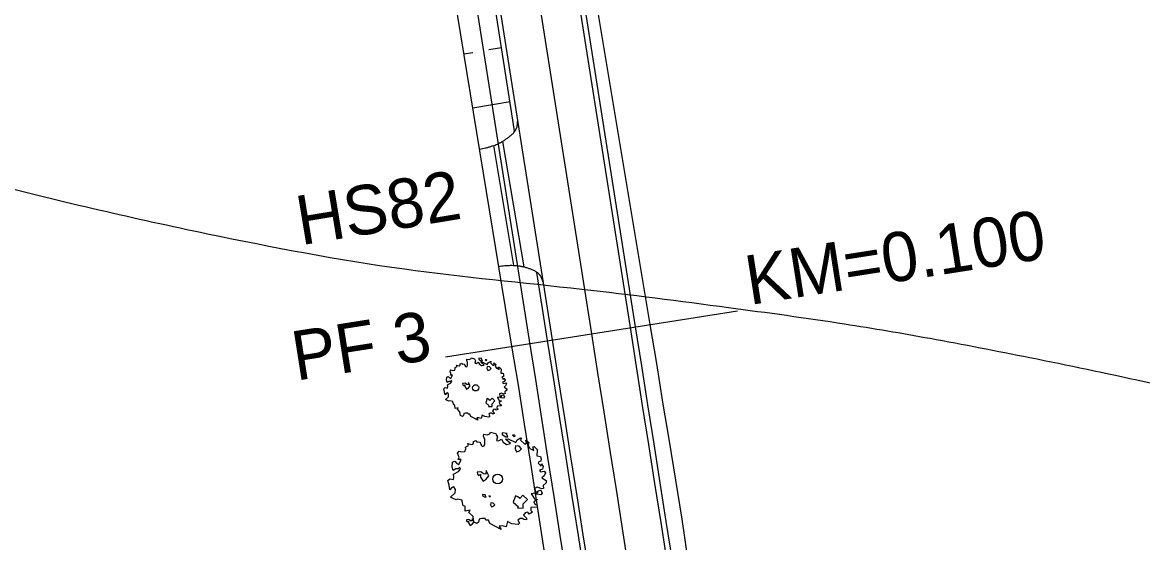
# Model space of a CAD drawing. Extents: x -477701 to -476785, y -1116511 to -1115314.
# Drawn here: x -477049.9 to -476993.1, y -1116046.9 to -1116020.5 of the extents above; entities that cross this region are included whole.
import ezdxf

# ---------------------------------------------------------------- set-up
doc = ezdxf.new("R2010")
doc.units = 0
for name, color, linetype in [('hrana_P', 7, 'Continuous'), ('hrana_R', 7, 'Continuous'), ('IP_RBK', 7, 'Continuous'), ('POLYGONY_SITUACE_PF', 7, 'Continuous'), ('POLYGONY_SITUACE_PF_POPISY', 7, 'Continuous'), ('popis', 7, 'Continuous'), ('svahování', 7, 'Continuous'), ('TP_HS', 7, 'Continuous'), ('Vrstevnice_hlavni', 7, 'Continuous'), ('Vrstevnice_vedlejsi', 7, 'Continuous')]:
    doc.layers.add(name, color=color, linetype=linetype)

msp = doc.modelspace()

# ---------------------------------------------------------------- linework, layer by layer
at = {"layer": 'hrana_P'}
for points in [[(-477018.038, -1116035.808), (-477021.004, -1116018.053)], [(-477025.047, -1116036.913), (-477027.968, -1116019.151)], [(-477017.702, -1116037.779), (-477018.038, -1116035.808)], [(-477024.724, -1116038.886), (-477025.047, -1116036.913)], [(-477017.388, -1116039.755), (-477017.702, -1116037.779)], [(-477024.411, -1116040.862), (-477024.724, -1116038.886)], [(-477017.053, -1116041.726), (-477017.388, -1116039.755)], [(-477024.099, -1116042.837), (-477024.411, -1116040.862)], [(-477016.736, -1116043.701), (-477017.053, -1116041.726)], [(-477023.795, -1116044.814), (-477024.099, -1116042.837)], [(-477016.423, -1116045.677), (-477016.736, -1116043.701)], [(-477023.49, -1116046.791), (-477023.795, -1116044.814)], [(-477016.123, -1116047.654), (-477016.423, -1116045.677)], [(-477023.184, -1116048.767), (-477023.49, -1116046.791)]]:
    msp.add_lwpolyline(points, dxfattribs=at)
at = {"layer": 'hrana_R'}
for points in [[(-477019.042, -1116035.966), (-477021.845, -1116018.185)], [(-477021.598, -1116018.147), (-477018.795, -1116035.927)], [(-477024.158, -1116036.628), (-477026.961, -1116018.847)], [(-477024.917, -1116025.985), (-477026.043, -1116018.847)], [(-477022.993, -1116036.589), (-477025.796, -1116018.808)], [(-477023.82, -1116018.497), (-477021.017, -1116036.277)], [(-477023.24, -1116036.628), (-477023.784, -1116033.172)], [(-477018.73, -1116037.941), (-477019.042, -1116035.966)], [(-477018.795, -1116035.927), (-477018.483, -1116037.903)], [(-477022.681, -1116038.564), (-477022.993, -1116036.589)], [(-477021.017, -1116036.277), (-477020.706, -1116038.253)], [(-477023.846, -1116038.603), (-477024.158, -1116036.628)], [(-477022.928, -1116038.603), (-477023.24, -1116036.628)], [(-477020.706, -1116038.253), (-477020.394, -1116040.229)], [(-477018.419, -1116039.917), (-477018.73, -1116037.941)], [(-477018.483, -1116037.903), (-477018.172, -1116039.878)], [(-477023.535, -1116040.579), (-477023.846, -1116038.603)], [(-477022.617, -1116040.579), (-477022.928, -1116038.603)], [(-477022.37, -1116040.54), (-477022.681, -1116038.564)], [(-477018.107, -1116041.893), (-477018.419, -1116039.917)], [(-477018.172, -1116039.878), (-477017.86, -1116041.854)], [(-477023.223, -1116042.554), (-477023.535, -1116040.579)], [(-477022.305, -1116042.554), (-477022.617, -1116040.579)], [(-477022.058, -1116042.516), (-477022.37, -1116040.54)], [(-477020.394, -1116040.229), (-477020.083, -1116042.204)], [(-477020.083, -1116042.204), (-477019.771, -1116044.18)], [(-477017.796, -1116043.868), (-477018.107, -1116041.893)], [(-477017.86, -1116041.854), (-477017.549, -1116043.829)], [(-477022.912, -1116044.53), (-477023.223, -1116042.554)], [(-477021.994, -1116044.53), (-477022.305, -1116042.554)], [(-477021.747, -1116044.491), (-477022.058, -1116042.516)], [(-477017.484, -1116045.844), (-477017.796, -1116043.868)], [(-477017.549, -1116043.829), (-477017.237, -1116045.805)], [(-477022.6, -1116046.506), (-477022.912, -1116044.53)], [(-477021.682, -1116046.506), (-477021.994, -1116044.53)], [(-477021.436, -1116046.467), (-477021.747, -1116044.491)], [(-477019.771, -1116044.18), (-477019.46, -1116046.155)], [(-477019.46, -1116046.155), (-477019.148, -1116048.131)], [(-477017.173, -1116047.819), (-477017.484, -1116045.844)], [(-477017.237, -1116045.805), (-477016.926, -1116047.781)], [(-477022.289, -1116048.481), (-477022.6, -1116046.506)], [(-477021.371, -1116048.481), (-477021.682, -1116046.506)], [(-477021.124, -1116048.442), (-477021.436, -1116046.467)]]:
    msp.add_lwpolyline(points, dxfattribs=at)
at = {"layer": 'IP_RBK'}
for points in [[(-477025.969, -1116037.759), (-477025.874, -1116037.832), (-477025.896, -1116037.915), (-477025.837, -1116038.028), (-477025.703, -1116038.089), (-477025.745, -1116037.98), (-477025.695, -1116037.964), (-477025.58, -1116038.088), (-477025.603, -1116038.081), (-477025.612, -1116038.271), (-477025.495, -1116038.284), (-477025.47, -1116038.367), (-477025.484, -1116038.443), (-477025.551, -1116038.459), (-477025.57, -1116038.504), (-477025.473, -1116038.602), (-477025.459, -1116038.522), (-477025.4, -1116038.614), (-477025.423, -1116038.7), (-477025.522, -1116038.732), (-477025.491, -1116038.792), (-477025.368, -1116038.766), (-477025.333, -1116038.825), (-477025.37, -1116038.913), (-477025.446, -1116038.986), (-477025.309, -1116039.068), (-477025.312, -1116039.146), (-477025.403, -1116039.23), (-477025.394, -1116039.329), (-477025.463, -1116039.344), (-477025.585, -1116039.286), (-477025.678, -1116039.317), (-477025.662, -1116039.419), (-477025.575, -1116039.473), (-477025.582, -1116039.419), (-477025.538, -1116039.395), (-477025.481, -1116039.383), (-477025.434, -1116039.481), (-477025.476, -1116039.538), (-477025.62, -1116039.519), (-477025.67, -1116039.487), (-477025.793, -1116039.504), (-477025.78, -1116039.509), (-477025.69, -1116039.669), (-477025.585, -1116039.682), (-477025.706, -1116039.761), (-477025.681, -1116039.838), (-477025.596, -1116039.874), (-477025.598, -1116039.937), (-477025.807, -1116039.948), (-477025.811, -1116040.05), (-477025.753, -1116040.1), (-477025.858, -1116040.16), (-477025.902, -1116040.095), (-477025.989, -1116040.115), (-477026.042, -1116040.195), (-477025.95, -1116040.289), (-477025.95, -1116040.345), (-477026.036, -1116040.332), (-477026.081, -1116040.303), (-477026.159, -1116040.306), (-477026.228, -1116040.359), (-477026.178, -1116040.461), (-477026.22, -1116040.5), (-477026.419, -1116040.479), (-477026.566, -1116040.401), (-477026.604, -1116040.574), (-477026.738, -1116040.539), (-477026.832, -1116040.549), (-477026.772, -1116040.657), (-477027.142, -1116040.466), (-477027.187, -1116040.362), (-477027.27, -1116040.358), (-477027.287, -1116040.31), (-477027.403, -1116040.307), (-477027.491, -1116040.325), (-477027.51, -1116040.425), (-477027.566, -1116040.47), (-477027.665, -1116040.419), (-477027.686, -1116040.237), (-477027.819, -1116040.107), (-477027.781, -1116040.036), (-477027.938, -1116040.064), (-477027.948, -1116039.907), (-477028.005, -1116039.89), (-477028.046, -1116039.746), (-477028.045, -1116039.712), (-477028.193, -1116039.672), (-477028.236, -1116039.696), (-477028.337, -1116039.659), (-477028.418, -1116039.607), (-477028.267, -1116039.473), (-477028.263, -1116039.366), (-477028.306, -1116039.274), (-477028.376, -1116039.297), (-477028.445, -1116039.378), (-477028.464, -1116039.225), (-477028.502, -1116039.067), (-477028.44, -1116039.011), (-477028.319, -1116039.038), (-477028.307, -1116038.958), (-477028.327, -1116038.861), (-477028.162, -1116038.776), (-477028.099, -1116038.703), (-477028.111, -1116038.642), (-477028.173, -1116038.692), (-477028.247, -1116038.692), (-477028.333, -1116038.746), (-477028.368, -1116038.634), (-477028.358, -1116038.472), (-477028.281, -1116038.441), (-477028.215, -1116038.518), (-477028.145, -1116038.544), (-477028.08, -1116038.409), (-477028.073, -1116038.386), (-477028.173, -1116038.384), (-477028.135, -1116038.309), (-477028.164, -1116038.262), (-477028.191, -1116038.179), (-477028.134, -1116038.113), (-477028.068, -1116038.141), (-477027.953, -1116038.13), (-477027.924, -1116038.041), (-477027.936, -1116037.986), (-477027.835, -1116037.93), (-477027.861, -1116037.87), (-477027.729, -1116037.898), (-477027.671, -1116037.865), (-477027.674, -1116037.798), (-477027.587, -1116037.769), (-477027.578, -1116037.814), (-477027.526, -1116037.81), (-477027.47, -1116037.826), (-477027.448, -1116037.851), (-477027.438, -1116037.894), (-477027.411, -1116037.932), (-477027.376, -1116037.959), (-477027.323, -1116037.943), (-477027.3, -1116037.879), (-477027.299, -1116037.738), (-477027.346, -1116037.629), (-477027.341, -1116037.562), (-477027.224, -1116037.581), (-477027.14, -1116037.553), (-477027.12, -1116037.503), (-477026.945, -1116037.542), (-477026.931, -1116037.586), (-477026.891, -1116037.647), (-477026.927, -1116037.773), (-477026.864, -1116037.778), (-477026.764, -1116037.722), (-477026.701, -1116037.823), (-477026.595, -1116037.894), (-477026.465, -1116037.866), (-477026.628, -1116037.723), (-477026.541, -1116037.716), (-477026.299, -1116037.829), (-477026.246, -1116037.743), (-477026.138, -1116037.678), (-477026.109, -1116037.691), (-477026.14, -1116037.758), (-477026.007, -1116037.889), (-477025.945, -1116037.861)], [(-477026.737, -1116037.573), (-477026.624, -1116037.645), (-477026.55, -1116037.654), (-477026.597, -1116037.555), (-477026.577, -1116037.54), (-477026.736, -1116037.517)], [(-477026.401, -1116037.594), (-477026.352, -1116037.645), (-477026.321, -1116037.62), (-477026.337, -1116037.598)], [(-477026.3, -1116037.944), (-477026.318, -1116038.045), (-477026.268, -1116038.141), (-477026.179, -1116038.108), (-477026.109, -1116038.041), (-477026.182, -1116037.954)], [(-477027.439, -1116038.868), (-477027.439, -1116038.96), (-477027.356, -1116039.089), (-477027.259, -1116039.027), (-477027.177, -1116038.915), (-477027.256, -1116038.748), (-477027.276, -1116038.861), (-477027.341, -1116038.85), (-477027.403, -1116038.805), (-477027.43, -1116038.785), (-477027.55, -1116038.8), (-477027.543, -1116038.86), (-477027.51, -1116038.909), (-477027.464, -1116038.89)], [(-477026.305, -1116039.563), (-477026.378, -1116039.773), (-477026.211, -1116039.928), (-477026.242, -1116039.962), (-477026.056, -1116039.967), (-477026.053, -1116039.826), (-477025.919, -1116039.683), (-477026.061, -1116039.549), (-477026.163, -1116039.658), (-477026.23, -1116039.595)], [(-477024.346, -1116041.676), (-477024.197, -1116041.79), (-477024.231, -1116041.919), (-477024.14, -1116042.095), (-477023.931, -1116042.191), (-477023.997, -1116042.02), (-477023.918, -1116041.996), (-477023.739, -1116042.189), (-477023.774, -1116042.178), (-477023.788, -1116042.474), (-477023.606, -1116042.494), (-477023.567, -1116042.624), (-477023.59, -1116042.742), (-477023.694, -1116042.766), (-477023.723, -1116042.837), (-477023.572, -1116042.99), (-477023.551, -1116042.866), (-477023.458, -1116043.009), (-477023.495, -1116043.143), (-477023.648, -1116043.193), (-477023.601, -1116043.287), (-477023.408, -1116043.245), (-477023.353, -1116043.338), (-477023.412, -1116043.475), (-477023.529, -1116043.588), (-477023.317, -1116043.717), (-477023.321, -1116043.839), (-477023.464, -1116043.969), (-477023.449, -1116044.123), (-477023.557, -1116044.147), (-477023.747, -1116044.056), (-477023.892, -1116044.105), (-477023.867, -1116044.263), (-477023.731, -1116044.348), (-477023.741, -1116044.264), (-477023.674, -1116044.226), (-477023.584, -1116044.208), (-477023.511, -1116044.361), (-477023.576, -1116044.45), (-477023.801, -1116044.42), (-477023.879, -1116044.369), (-477024.07, -1116044.396), (-477024.05, -1116044.404), (-477023.91, -1116044.653), (-477023.746, -1116044.674), (-477023.935, -1116044.797), (-477023.897, -1116044.918), (-477023.764, -1116044.974), (-477023.767, -1116045.072), (-477024.092, -1116045.088), (-477024.099, -1116045.248), (-477024.009, -1116045.325), (-477024.172, -1116045.419), (-477024.24, -1116045.318), (-477024.377, -1116045.35), (-477024.459, -1116045.473), (-477024.316, -1116045.621), (-477024.315, -1116045.708), (-477024.45, -1116045.688), (-477024.52, -1116045.642), (-477024.641, -1116045.647), (-477024.748, -1116045.73), (-477024.672, -1116045.889), (-477024.737, -1116045.95), (-477025.047, -1116045.917), (-477025.277, -1116045.795), (-477025.336, -1116046.065), (-477025.544, -1116046.01), (-477025.691, -1116046.027), (-477025.598, -1116046.195), (-477026.175, -1116045.896), (-477026.244, -1116045.734), (-477026.373, -1116045.728), (-477026.401, -1116045.653), (-477026.582, -1116045.649), (-477026.719, -1116045.676), (-477026.748, -1116045.833), (-477026.835, -1116045.903), (-477026.99, -1116045.823), (-477027.023, -1116045.539), (-477027.231, -1116045.337), (-477027.171, -1116045.225), (-477027.415, -1116045.27), (-477027.431, -1116045.025), (-477027.52, -1116044.998), (-477027.583, -1116044.774), (-477027.582, -1116044.721), (-477027.813, -1116044.658), (-477027.88, -1116044.696), (-477028.038, -1116044.638), (-477028.164, -1116044.557), (-477027.928, -1116044.347), (-477027.921, -1116044.181), (-477027.99, -1116044.038), (-477028.098, -1116044.073), (-477028.205, -1116044.2), (-477028.236, -1116043.962), (-477028.295, -1116043.715), (-477028.198, -1116043.628), (-477028.009, -1116043.669), (-477027.991, -1116043.546), (-477028.023, -1116043.395), (-477027.765, -1116043.261), (-477027.667, -1116043.147), (-477027.685, -1116043.053), (-477027.782, -1116043.13), (-477027.896, -1116043.13), (-477028.032, -1116043.214), (-477028.086, -1116043.04), (-477028.071, -1116042.787), (-477027.951, -1116042.739), (-477027.848, -1116042.859), (-477027.739, -1116042.899), (-477027.637, -1116042.689), (-477027.626, -1116042.653), (-477027.781, -1116042.651), (-477027.723, -1116042.533), (-477027.768, -1116042.46), (-477027.811, -1116042.33), (-477027.721, -1116042.228), (-477027.617, -1116042.272), (-477027.439, -1116042.255), (-477027.394, -1116042.116), (-477027.413, -1116042.03), (-477027.254, -1116041.943), (-477027.295, -1116041.849), (-477027.09, -1116041.892), (-477026.998, -1116041.84), (-477027.003, -1116041.736), (-477026.868, -1116041.691), (-477026.854, -1116041.761), (-477026.772, -1116041.755), (-477026.685, -1116041.781), (-477026.651, -1116041.819), (-477026.636, -1116041.886), (-477026.593, -1116041.945), (-477026.539, -1116041.987), (-477026.456, -1116041.963), (-477026.42, -1116041.863), (-477026.419, -1116041.643), (-477026.493, -1116041.473), (-477026.484, -1116041.368), (-477026.302, -1116041.399), (-477026.171, -1116041.354), (-477026.14, -1116041.276), (-477025.868, -1116041.337), (-477025.846, -1116041.405), (-477025.784, -1116041.501), (-477025.839, -1116041.698), (-477025.74, -1116041.706), (-477025.584, -1116041.618), (-477025.487, -1116041.776), (-477025.321, -1116041.886), (-477025.118, -1116041.843), (-477025.373, -1116041.62), (-477025.237, -1116041.608), (-477024.86, -1116041.785), (-477024.778, -1116041.65), (-477024.609, -1116041.55), (-477024.564, -1116041.57), (-477024.612, -1116041.674), (-477024.404, -1116041.878), (-477024.308, -1116041.834)], [(-477025.543, -1116041.385), (-477025.366, -1116041.497), (-477025.251, -1116041.512), (-477025.325, -1116041.358), (-477025.293, -1116041.334), (-477025.541, -1116041.299)], [(-477025.018, -1116041.418), (-477024.943, -1116041.497), (-477024.894, -1116041.459), (-477024.919, -1116041.425)], [(-477024.862, -1116041.965), (-477024.889, -1116042.121), (-477024.811, -1116042.272), (-477024.673, -1116042.22), (-477024.564, -1116042.116), (-477024.677, -1116041.979)], [(-477026.637, -1116043.405), (-477026.637, -1116043.548), (-477026.509, -1116043.749), (-477026.357, -1116043.653), (-477026.23, -1116043.478), (-477026.352, -1116043.218), (-477026.382, -1116043.394), (-477026.485, -1116043.376), (-477026.581, -1116043.306), (-477026.623, -1116043.276), (-477026.81, -1116043.298), (-477026.799, -1116043.392), (-477026.748, -1116043.468), (-477026.676, -1116043.438)], [(-477026.55, -1116044.48), (-477026.437, -1116044.552), (-477026.363, -1116044.562), (-477026.41, -1116044.463), (-477026.39, -1116044.448), (-477026.549, -1116044.425)], [(-477026.214, -1116044.502), (-477026.165, -1116044.552), (-477026.134, -1116044.528), (-477026.15, -1116044.506)], [(-477024.869, -1116044.489), (-477024.983, -1116044.817), (-477024.722, -1116045.058), (-477024.771, -1116045.111), (-477024.481, -1116045.118), (-477024.476, -1116044.898), (-477024.267, -1116044.676), (-477024.489, -1116044.467), (-477024.648, -1116044.637), (-477024.752, -1116044.539)], [(-477026.113, -1116044.852), (-477026.13, -1116044.953), (-477026.081, -1116045.049), (-477025.992, -1116045.016), (-477025.922, -1116044.949), (-477025.995, -1116044.861)], [(-477027.252, -1116045.776), (-477027.252, -1116045.867), (-477027.169, -1116045.997), (-477027.072, -1116045.935), (-477026.99, -1116045.823), (-477027.069, -1116045.656), (-477027.088, -1116045.769), (-477027.154, -1116045.757), (-477027.216, -1116045.712), (-477027.243, -1116045.693), (-477027.363, -1116045.707), (-477027.356, -1116045.768), (-477027.323, -1116045.817), (-477027.277, -1116045.797)]]:
    msp.add_lwpolyline(points, close=True, dxfattribs=at)
for centre, radius in [((-477026.886, -1116039.022), 0.158), ((-477025.775, -1116043.645), 0.247)]:
    msp.add_circle(centre, radius, dxfattribs=at)
at = {"layer": 'POLYGONY_SITUACE_PF'}
msp.add_lwpolyline([(-477028.425, -1116037.445), (-477021.017, -1116036.277), (-477013.608, -1116035.109)], dxfattribs=at)
at = {"layer": 'svahování'}
for points in [[(-477025.581, -1116021.773), (-477026.217, -1116021.879)], [(-477025.581, -1116021.773), (-477026.217, -1116021.879)], [(-477025.581, -1116021.773), (-477026.217, -1116021.879)], [(-477027.484, -1116022.092), (-477027.04, -1116022.017)], [(-477027.484, -1116022.092), (-477027.04, -1116022.017)], [(-477027.484, -1116022.092), (-477027.04, -1116022.017)], [(-477025.148, -1116024.525), (-477027.032, -1116024.841)], [(-477025.148, -1116024.525), (-477027.032, -1116024.841)], [(-477025.148, -1116024.525), (-477027.032, -1116024.841)]]:
    msp.add_lwpolyline(points, dxfattribs=at)
at = {"layer": 'TP_HS'}
for p, q in [((-477025.993, -1116026.74), (-477024.968, -1116032.81)), ((-477025.523, -1116026.524), (-477024.448, -1116032.883))]:
    msp.add_line(p, q, dxfattribs=at)
for points in [[(-477026.69, -1116026.92), (-477026.538, -1116026.893), (-477026.388, -1116026.857), (-477026.239, -1116026.816), (-477026.09, -1116026.772), (-477025.968, -1116026.732), (-477025.849, -1116026.685), (-477025.732, -1116026.633), (-477025.674, -1116026.605), (-477025.616, -1116026.576), (-477025.473, -1116026.494), (-477025.337, -1116026.403), (-477025.206, -1116026.303), (-477025.142, -1116026.25), (-477025.078, -1116026.195), (-477025.01, -1116026.133), (-477024.948, -1116026.066), (-477024.893, -1116025.994), (-477024.868, -1116025.955), (-477024.845, -1116025.914), (-477024.792, -1116025.783), (-477024.768, -1116025.647), (-477024.756, -1116025.42)], [(-477025.714, -1116032.854), (-477025.643, -1116032.844), (-477025.489, -1116032.828), (-477025.334, -1116032.817), (-477025.257, -1116032.814), (-477025.179, -1116032.81), (-477025.051, -1116032.808), (-477024.923, -1116032.813), (-477024.796, -1116032.823), (-477024.732, -1116032.831), (-477024.668, -1116032.839), (-477024.505, -1116032.869), (-477024.347, -1116032.911), (-477024.19, -1116032.962), (-477024.112, -1116032.991), (-477024.034, -1116033.021), (-477023.949, -1116033.058), (-477023.869, -1116033.1), (-477023.793, -1116033.15), (-477023.757, -1116033.179), (-477023.721, -1116033.21), (-477023.672, -1116033.261), (-477023.649, -1116033.288), (-477023.628, -1116033.316), (-477023.561, -1116033.437), (-477023.475, -1116033.648)]]:
    msp.add_spline(points, degree=3, dxfattribs=at)
at = {"layer": 'Vrstevnice_hlavni'}
msp.add_spline([(-477172.035, -1116047.879), (-477163.676, -1116040.241), (-477159.76, -1116037.23), (-477156.106, -1116035.027), (-477152.715, -1116033.631), (-477147.141, -1116031.826), (-477139.385, -1116029.612), (-477129.445, -1116026.988), (-477120.227, -1116024.981), (-477111.728, -1116023.589), (-477103.95, -1116022.815), (-477096.913, -1116022.156), (-477090.617, -1116021.614), (-477085.062, -1116021.187), (-477080.908, -1116021.045), (-477078.156, -1116021.187), (-477076.806, -1116021.614), (-477071.912, -1116023.001), (-477063.473, -1116025.348), (-477051.49, -1116028.656), (-477040.501, -1116031.204), (-477030.507, -1116032.99), (-477021.507, -1116034.016), (-477014.063, -1116034.945), (-477008.174, -1116035.776), (-477003.84, -1116036.51), (-476998.776, -1116037.485), (-476992.982, -1116038.7), (-476986.457, -1116040.157), (-476979.838, -1116041.295), (-476973.124, -1116042.116), (-476966.315, -1116042.62), (-476959.327, -1116044.222), (-476952.16, -1116046.923), (-476937.468, -1116054.524)], degree=3, dxfattribs=at)
at = {"layer": 'Vrstevnice_vedlejsi'}
msp.add_spline([(-476871.124, -1116081.671), (-476875.315, -1116073.874), (-476878.296, -1116068.415), (-476880.067, -1116065.293), (-476880.628, -1116064.508), (-476881.186, -1116063.798), (-476881.742, -1116063.162), (-476882.295, -1116062.601), (-476885.012, -1116060.502), (-476889.892, -1116056.865), (-476896.937, -1116051.69), (-476903.358, -1116047.14), (-476909.156, -1116043.213), (-476914.331, -1116039.91), (-476921.333, -1116036.09), (-476930.161, -1116031.752), (-476940.815, -1116026.896), (-476948.811, -1116023.462), (-476954.149, -1116021.449), (-476956.827, -1116020.859), (-476958.832, -1116020.442), (-476960.164, -1116020.201), (-476960.822, -1116020.133), (-476965.486, -1116019.907), (-476974.155, -1116019.521), (-476986.831, -1116018.977), (-476999.015, -1116018.304), (-477010.707, -1116017.503), (-477021.909, -1116016.574), (-477030.087, -1116015.739), (-477035.242, -1116014.998), (-477037.374, -1116014.351), (-477040.563, -1116013.078), (-477044.81, -1116011.179), (-477050.114, -1116008.653), (-477056.327, -1116006.124), (-477063.447, -1116003.592), (-477071.477, -1116001.056), (-477078.813, -1115999.518), (-477085.456, -1115998.977), (-477086.943, -1115999.041), (-477088.431, -1115999.203), (-477089.918, -1115999.366), (-477091.406, -1115999.433), (-477097.834, -1115998.922), (-477104.739, -1115997.442), (-477106.596, -1115996.868), (-477108.424, -1115996.21), (-477110.256, -1115995.556), (-477112.123, -1115994.993), (-477119.996, -1115993.688), (-477128.358, -1115993.525), (-477137.21, -1115994.504), (-477144.604, -1115995.693), (-477150.541, -1115997.09), (-477155.02, -1115998.695), (-477161.179, -1116002.182), (-477169.018, -1116007.55), (-477178.537, -1116014.8), (-477186.155, -1116020.752), (-477191.872, -1116025.406), (-477195.689, -1116028.763), (-477198.973, -1116032.744), (-477200.065, -1116034.354)], degree=3, dxfattribs=at)

# ---------------------------------------------------------------- texts
at = {"layer": 'POLYGONY_SITUACE_PF_POPISY'}
for s, p in [('KM=0.100', (-477012.991, -1116034.824)), ('PF 3', (-477035.995, -1116038.663))]:
    msp.add_text(s, height=2.5, rotation=8.9589, dxfattribs=at).set_placement(p)
at = {"layer": 'popis'}
msp.add_text('HS82', height=2.5, rotation=9.4165, dxfattribs=at).set_placement((-477035.756, -1116031.795))

doc.saveas('drawing.dxf')
